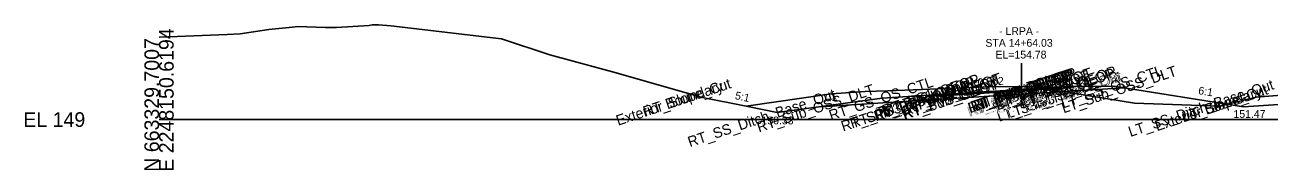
# Model space of a CAD drawing. Extents: x -26 to 2603, y -10 to 9566.
# Drawn here: x -25.7 to 212.6, y 6490.3 to 6518.1 of the extents above; entities that cross this region are included whole.
import ezdxf

# ---------------------------------------------------------------- set-up
doc = ezdxf.new("R2010")
doc.units = 0
for name, color, linetype in [('Default', 7, 'Continuous'), ('Exist Cross Section Cell', 7, 'Continuous'), ('Exist XS Ground Line', 7, 'Continuous'), ('Prop CMT Concrete Structures', 7, 'Continuous'), ('Prop CMT Guardrail Graphics', 7, 'Continuous'), ('Prop CMT Pvmt Course 2', 7, 'Continuous'), ('Prop CMT Pvmt Surface', 7, 'Continuous'), ('Prop CMT Pvmt Surface Overlay', 7, 'Continuous'), ('Prop CMT Pvmt Surface Shoulder', 7, 'Continuous'), ('Prop CMT Shld Paved Course 1', 7, 'Continuous'), ('Prop CMT Shld Paved Course 2', 7, 'Continuous'), ('Prop CMT Shld Paved Course 3', 7, 'Continuous'), ('Prop CMT Slope Grass', 7, 'Continuous'), ('Prop CMT Subgrade Earthwork', 7, 'Continuous'), ('Prop XS Ditch Standard Text', 7, 'Continuous'), ('Prop XS SE Text', 7, 'Continuous'), ('Prop XS Side Slope Text', 7, 'Continuous'), ('Prop XS Vertical Lines Alignments', 7, 'Continuous'), ('Scratch_Level_9', 7, 'Continuous')]:
    doc.layers.add(name, color=color, linetype=linetype)

msp = doc.modelspace()

# ---------------------------------------------------------------- linework, layer by layer
at = {"layer": 'Exist Cross Section Cell'}
msp.add_line((0, 6500), (300, 6500), dxfattribs=at)
at = {"layer": 'Exist XS Ground Line'}
for p, q in [((15.53, 6516.46), (21.01, 6517.23)), ((21.01, 6517.23), (25.55, 6517.7)), ((25.55, 6517.7), (26.56, 6517.85)), ((26.56, 6517.85), (31.84, 6517.66)), ((31.84, 6517.66), (33.24, 6517.63)), ((33.24, 6517.63), (34, 6517.63)), ((34, 6517.63), (40.23, 6518.04)), ((40.23, 6518.04), (40.81, 6518.14)), ((40.81, 6518.14), (42.02, 6518.15)), ((42.02, 6518.15), (44.38, 6517.95)), ((44.38, 6517.95), (65.57, 6515.46)), ((0, 6515.82), (3.45, 6515.93)), ((3.45, 6515.93), (13.06, 6516.32)), ((13.06, 6516.32), (15.53, 6516.46)), ((65.57, 6515.46), (74.83, 6512.4)), ((74.83, 6512.4), (87.54, 6508.97)), ((87.54, 6508.97), (102.93, 6504.53)), ((102.93, 6504.53), (103.72, 6504.32))]:
    msp.add_line(p, q, dxfattribs=at)
for points in [[(135.23, 6505.36), (128.75, 6504.93), (112.42, 6502.55)], [(139.55, 6505.53), (135.23, 6505.36)], [(152.45, 6506.03), (139.55, 6505.53)], [(152.45, 6506.03), (156.75, 6506.19)], [(156.75, 6506.19), (161.05, 6506.36)], [(161.05, 6506.36), (167.5, 6506.25), (186.77, 6503.12)], [(218.11, 6504.93), (210.1, 6504.29)], [(112.42, 6502.55), (103.72, 6504.32)], [(186.77, 6503.12), (203.16, 6502.56)], [(207.45, 6503.63), (203.16, 6502.56)], [(210.1, 6504.29), (207.45, 6503.63)], [(207.45, 6503.63), (207.45, 6503.63)]]:
    msp.add_lwpolyline(points, dxfattribs=at)
at = {"layer": 'Prop CMT Concrete Structures'}
for points in [[(165.16, 6504.87), (151.86, 6504.03)], [(151.86, 6504.02), (165.16, 6504.86)], [(165.16, 6504.87), (169.59, 6505.15)], [(169.59, 6505.14), (165.16, 6504.86)], [(165.16, 6504.86), (165.16, 6504.87)], [(169.59, 6505.15), (169.59, 6505.14)], [(151.86, 6504.03), (151.86, 6504.02)]]:
    msp.add_lwpolyline(points, dxfattribs=at)
at = {"layer": 'Prop CMT Guardrail Graphics'}
for points in [[(169.59, 6505.15), (174.97, 6505.49), (175.52, 6505.52), (175.53, 6505.51)], [(175.53, 6505.51), (169.59, 6505.14)], [(169.59, 6505.14), (169.59, 6505.15)], [(151.86, 6504.03), (146.29, 6503.69), (145.73, 6503.65), (145.72, 6503.64)], [(145.72, 6503.64), (151.86, 6504.02)], [(151.86, 6504.02), (151.86, 6504.03)]]:
    msp.add_lwpolyline(points, dxfattribs=at)
at = {"layer": 'Prop CMT Pvmt Course 2'}
for points in [[(174.03, 6506.34), (182.85, 6506.43), (207.7, 6502.47)], [(174.03, 6506.34), (182.85, 6506.43), (207.7, 6502.47)], [(174.03, 6506.34), (182.85, 6506.43), (207.7, 6502.47)], [(247, 6505.05), (207.7, 6502.47)], [(247, 6505.05), (207.7, 6502.47)], [(247, 6505.05), (207.7, 6502.47)], [(118.38, 6501.33), (112.42, 6502.55)], [(118.38, 6501.33), (112.42, 6502.55)], [(118.38, 6501.33), (112.42, 6502.55)], [(147.4, 6504.67), (138.49, 6504.12), (118.38, 6501.33)], [(147.4, 6504.67), (138.49, 6504.12), (118.38, 6501.33)], [(147.4, 6504.67), (138.49, 6504.12), (118.38, 6501.33)]]:
    msp.add_lwpolyline(points, dxfattribs=at)
at = {"layer": 'Prop CMT Pvmt Surface'}
for points in [[(165.16, 6505.78), (151.86, 6504.95)], [(165.16, 6505.78), (169.59, 6506.06)]]:
    msp.add_lwpolyline(points, dxfattribs=at)
at = {"layer": 'Prop CMT Pvmt Surface Shoulder'}
for points in [[(165.16, 6505.78), (151.86, 6504.95)], [(151.86, 6504.7), (165.16, 6505.53)], [(151.86, 6504.95), (151.86, 6504.7)], [(165.16, 6505.78), (169.59, 6506.06)], [(169.59, 6505.81), (165.16, 6505.53)], [(165.16, 6505.53), (165.16, 6505.78)], [(169.59, 6506.06), (169.59, 6505.81)]]:
    msp.add_lwpolyline(points, dxfattribs=at)
msp.add_lwpolyline([(165.16, 6505.53), (165.16, 6505.66), (165.16, 6505.66), (165.16, 6505.53)], close=True, dxfattribs=at)
at = {"layer": 'Prop CMT Shld Paved Course 1'}
for points in [[(151.86, 6504.95), (147.4, 6504.67), (147.1, 6504.4)], [(151.86, 6504.7), (151.86, 6504.95)], [(169.59, 6506.06), (174.03, 6506.34), (174.28, 6506.11)], [(174.28, 6506.11), (169.59, 6505.81)], [(169.59, 6505.81), (169.59, 6506.06)], [(147.1, 6504.4), (151.86, 6504.7)]]:
    msp.add_lwpolyline(points, dxfattribs=at)
at = {"layer": 'Prop CMT Shld Paved Course 2'}
for points in [[(169.59, 6505.81), (174.28, 6506.11), (174.97, 6505.49)], [(169.59, 6505.15), (169.59, 6505.81)], [(174.97, 6505.49), (169.59, 6505.15)], [(151.86, 6504.7), (147.1, 6504.4), (146.29, 6503.69)], [(146.29, 6503.69), (151.86, 6504.03)], [(151.86, 6504.03), (151.86, 6504.7)]]:
    msp.add_lwpolyline(points, dxfattribs=at)
at = {"layer": 'Prop CMT Shld Paved Course 3'}
for points in [[(165.16, 6504.86), (151.86, 6504.02)], [(165.16, 6504.86), (151.86, 6504.02)], [(165.16, 6504.86), (169.59, 6505.14)], [(165.16, 6504.86), (169.59, 6505.14)], [(169.59, 6505.14), (175.53, 6505.51)], [(169.59, 6505.14), (175.53, 6505.51)], [(175.53, 6505.51), (184.85, 6506.11)], [(175.53, 6505.51), (184.85, 6506.11)], [(145.72, 6503.64), (126.56, 6502.46)], [(145.72, 6503.64), (126.56, 6502.46)], [(151.86, 6504.02), (145.72, 6503.64)], [(151.86, 6504.02), (145.72, 6503.64)]]:
    msp.add_lwpolyline(points, dxfattribs=at)
at = {"layer": 'Prop CMT Slope Grass'}
for points in [[(165.16, 6505.53), (151.86, 6504.7)], [(151.86, 6504.03), (165.16, 6504.87)], [(165.16, 6505.53), (169.59, 6505.81)], [(165.16, 6504.87), (165.16, 6505.53)], [(169.59, 6505.15), (165.16, 6504.87)], [(169.59, 6505.81), (169.59, 6505.15)], [(151.86, 6504.7), (151.86, 6504.03)]]:
    msp.add_lwpolyline(points, dxfattribs=at)
at = {"layer": 'Prop CMT Subgrade Earthwork'}
for points in [[(151.86, 6504.95), (147.4, 6504.67)], [(169.59, 6506.06), (174.03, 6506.34)]]:
    msp.add_lwpolyline(points, dxfattribs=at)
at = {"layer": 'Prop XS Vertical Lines Alignments'}
msp.add_line((165.17, 6510.78), (165.17, 6502.78), dxfattribs=at)

# ---------------------------------------------------------------- texts
at = {"layer": 'Default'}
msp.add_text('-', height=0.0001, dxfattribs=at).set_placement((0, 6500))
msp.add_text('-', height=0.0001, dxfattribs=at).set_placement((0, 6500))
msp.add_text('-', height=0.0001, dxfattribs=at).set_placement((0, 6500))
at = {"layer": 'Exist Cross Section Cell'}
for s, p in [('E 2248150.6194', (2.8, 6490)), ('N 663329.7007', (0, 6490))]:
    msp.add_text(s, height=2.8, rotation=90, dxfattribs=at).set_placement(p)
msp.add_text('EL 149', height=2.8, dxfattribs=at).set_placement((-26, 6498.6))
at = {"layer": 'Prop CMT Pvmt Surface Overlay'}
msp.add_text('EL=154.78', height=1.5, dxfattribs=at).set_placement((160.18, 6511.7))
at = {"layer": 'Prop XS Ditch Standard Text'}
for s, p in [('150.33', (115.37, 6499.08)), ('151.47', (205.75, 6500.33))]:
    msp.add_text(s, height=1.5, dxfattribs=at).set_placement(p)
at = {"layer": 'Prop XS SE Text'}
msp.add_text('0.062', height=1.5, rotation=3.5585, dxfattribs=at).set_placement((156.8, 6506.38))
at = {"layer": 'Prop XS Side Slope Text'}
for s, rotation, p in [('5:1', 347.6758, (110.2, 6503.94)), ('7:1', 7.8975, (127.15, 6503.3)), ('6:1', 350.9652, (198.94, 6504.87))]:
    msp.add_text(s, height=1.5, rotation=rotation, dxfattribs=at).set_placement(p)
at = {"layer": 'Prop XS Vertical Lines Alignments'}
for s, p in [('- LRPA -', (160.87, 6516.2)), ('STA 14+64.03', (158.25, 6513.95))]:
    msp.add_text(s, height=1.5, dxfattribs=at).set_placement(p)
at = {"layer": 'Scratch_Level_9'}
for s, p in [('RT_PV2_OEEOP', (155.29, 6501.19)), ('RT_PV1_OEEOP', (155.82, 6501.49)), ('LT_PV1_OEEOP', (155.87, 6501.51)), ('RT_PV1_IEEOP', (156.44, 6501.7)), ('LT_PV1_IEEOP', (156.48, 6501.71)), ('LT_PV2_OEOT', (160.59, 6501.76)), ('LT_PV1_OEOT', (161.12, 6502.19)), ('LT_PS2_OEOP', (165.34, 6502.08)), ('LT_PS1_OEOP', (165.62, 6502.49)), ('LT_GS_OS_CTL', (173.09, 6502.12)), ('LT_Sub_OSS_DLT', (173.22, 6501.18)), ('RT_Slope_Cut', (93.08, 6500.53)), ('RT_GS_OS_CTL', (128.68, 6499.79)), ('RT_Sub_Trench_Out', (131.01, 6497.68)), ('RT_PS3_Shelf_Out', (132.71, 6498.26)), ('RT_PS3_OEOP', (137.3, 6499.63)), ('RT_PS2_OEOP', (138.11, 6500.35)), ('RT_PS1_OEOP', (138.95, 6500.8)), ('RT_Sub_OEOT', (142.72, 6499.92)), ('RT_PV2_OEOT', (142.81, 6500.63)), ('RT_PV3_OEOT', (142.81, 6499.96)), ('RT_PV1_OEOT', (143.34, 6501.06)), ('RT_Sub_OEEOP', (155.2, 6500.48)), ('LT_Sub_OEEOP', (155.24, 6500.5)), ('RT_PV3_OEEOP', (155.29, 6500.52)), ('LT_PV2_OEEOP', (155.33, 6501.21)), ('LT_PV3_OEEOP', (155.33, 6500.54)), ('RT_PV2_IEEOP', (155.9, 6501.39)), ('LT_PV2_IEEOP', (155.94, 6501.41)), ('PV2_PGL', (159.69, 6502.66)), ('PV1_PGL', (160.23, 6503.09)), ('LT_Sub_OEOT', (160.5, 6501.05)), ('LT_PV3_OEOT', (160.59, 6501.09)), ('LT_Sub_Trench_Out', (160.86, 6499.57)), ('LT_PS3_Shelf_Out', (162.54, 6500.14)), ('LT_PS3_OEOP', (166.02, 6501.45)), ('LT_SS_Ditch_Base_Out', (186.01, 6496.65)), ('Exterior Boundary', (87.91, 6498.8)), ('RT_SS_Ditch_Base_Out', (101.65, 6494.7)), ('RT_Sub_OSS_DLT', (114.88, 6497.51)), ('Exterior Boundary', (191.1, 6497.76)), ('LT_Slope_Cut', (196.31, 6499.5))]:
    msp.add_text(s, height=2, rotation=18.4332, dxfattribs=at).set_placement(p)

doc.saveas('drawing.dxf')
